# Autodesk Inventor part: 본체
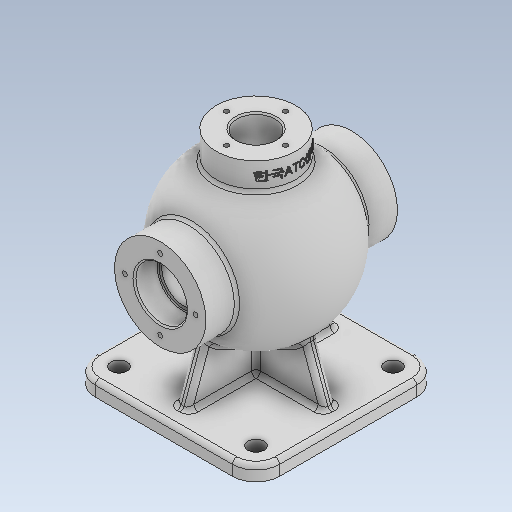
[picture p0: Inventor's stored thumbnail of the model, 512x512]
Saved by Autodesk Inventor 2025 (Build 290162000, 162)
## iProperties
Created: 2024-07
Part Number: 본체
Material: 일반
Document SubType Name: Modeling
Designer: 미서니
Density: 1 g/cm^3
Appearance: 기본값
Author: 미서니
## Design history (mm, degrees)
sketch "스케치1"
  geometry: L1 (0, -75.794)-(0, 75.794); A1 r 54 centre (0, 0) between (0, 54) and (0, -54); 4 further points
  constraints: 2 coincident, 2 end point, 2 point on circle, 2 point on line, 1 centre point, 1 midpoint, 1 vertical
  dimensions: "d3" = 54 radius of A1
revolve "회전1" sketch "스케치1" stored, may be unused: angle "d1" = 90 deg
sketch "스케치2"
  geometry: C1 r 31 at (0, 0); 1 further point
  constraints: 1 centre point, 1 coincident
  dimensions: "d2" = 62 diameter of C1
extrude "돌출1" join sketch "스케치2" stored distance "d4" = 130; taper "d5" = 0 deg
sketch "스케치3"
  geometry: C1 r 27 at (0, 0); 1 further point
  constraints: 1 centre point, 1 coincident
  dimensions: "d6" = 54 diameter of C1
extrude "돌출2" join sketch "스케치3" distance "d7" = 65; taper "d8" = 0 deg
node "작업 평면1"
sketch "스케치4"
  geometry: L1 (62.5, -62.5)-(-62.5, -62.5); L2 (-62.5, -62.5)-(-62.5, 62.5); L3 (-62.5, 62.5)-(62.5, 62.5); L4 (62.5, 62.5)-(62.5, -62.5); L5 (62.5, -62.5)-(-62.5, 62.5); L6 (-62.5, -62.5)-(62.5, 62.5); 1 further point
  constraints: 12 end point, 2 midpoint, 2 parallel, 1 horizontal, 1 perpendicular
  dimensions: "d10" = 125 distance of L2.end L3.end; "d11" = 125 distance of L1.end L2.end
extrude "돌출3" join sketch "스케치4" distance "d12" = 10; taper "d13" = 0 deg
fillet "모깎기1" dims "d14" = 16
node "작업 평면2"
sketch "스케치5"
  geometry: L1 (50.5, 4)-(-50.5, 4); L2 (-50.5, 4)-(-50.5, -4); L3 (-50.5, -4)-(50.5, -4); L4 (50.5, -4)-(50.5, 4); L5 (50.5, 4)-(-50.5, -4); L6 (-50.5, 4)-(50.5, -4); L7 (4, 50.5)-(-4, 50.5); L8 (-4, 50.5)-(-4, -50.5); L9 (-4, -50.5)-(4, -50.5); L10 (4, -50.5)-(4, 50.5); L11 (4, 50.5)-(-4, -50.5); L12 (-4, 50.5)-(4, -50.5); L13 (-62.5, 46.5)-(-62.5, -46.5) reference; L14 (-46.5, -62.5)-(46.5, -62.5) reference; 5 further points
  constraints: 24 end point, 4 midpoint, 4 parallel, 2 horizontal, 2 perpendicular
  dimensions: "d16" = 8 distance of L1.end L2.end; "d17" = 8 distance of L7.start L7.end; "d18" = 12 distance between parallel lines of L13 L2; "d19" = 12 distance between parallel lines of L14 L9
extrude "돌출4" join sketch "스케치5" stored distance "d20" = 10; taper "d21" = 0 deg
feature "면 기울기1" dims angle "d22" = 20 deg
fillet "모깎기2" dims "d23" = 3
fillet "모깎기3" dims "d24" = 3
sketch "스케치6"
  geometry: L1 (0, 159.291)-(0, -194.33); A1 r 44 centre (0, 0) between (0, 44) and (0, -44); 1 further point
  constraints: 3 point on line, 2 end point, 2 point on circle, 1 centre point, 1 coincident, 1 vertical
  dimensions: "d25" = 44 radius of A1
revolve "회전2" sketch "스케치6" stored, may be unused: angle "d26" = 90 deg
sketch "스케치7"
  geometry: C1 r 31 at (0, 0) reference; 2 further points
  constraints: 1 coincident
hole "구멍1" sketch "스케치7" at (0, 0) diameter "d27" = 30; stored, may be unused: countersink angle "d31" = 90 deg, drill point angle "d33" = 0 deg; dims "d28" = 6, "d29" = 4, "d30" = 2, "d32" = 8
sketch "스케치9"
  geometry: C1 r 31 at (0, 0) reference; 2 further points
  constraints: 1 coincident
hole "구멍3" sketch "스케치9" at (0, 0) diameter "d41" = 35; stored, may be unused: countersink angle "d45" = 90 deg, drill point angle "d47" = 0 deg; dims "d42" = 6, "d43" = 4, "d44" = 2, "d46" = 16
sketch "스케치10"
  geometry: C1 r 31 at (0, 0) reference; 2 further points
  constraints: 1 coincident
hole "구멍4" sketch "스케치10" at (0, 0) diameter "d48" = 35; stored, may be unused: countersink angle "d52" = 90 deg, drill point angle "d54" = 0 deg; dims "d49" = 6, "d50" = 4, "d51" = 2, "d53" = 16
sketch "스케치11"
  geometry: C1 r 27 at (0, 0) reference; 2 further points
  constraints: 1 coincident
hole "구멍5" sketch "스케치11" at (0, 0) diameter "d63" = 26; stored, may be unused: countersink angle "d67" = 90 deg, drill point angle "d69" = 0 deg; dims "d64" = 6, "d65" = 4, "d66" = 2, "d68" = 16
chamfer "모따기1" distance "d70" = 1; stored, may be unused: second distance "d71" = 2, angle "d72" = 45 deg
fillet "모깎기4" dims "d73" = 0.6
sketch "스케치12" dims "d74" = 48
  geometry: L1 (0, 0)-(0, 24); 1 further point
  constraints: 2 end point, 1 coincident, 1 vertical, 1 vertical alignment, 2 other
sketch "스케치13" dims "d75" = 48
  geometry: L1 (0, 0)-(0, 24); 1 further point
  constraints: 2 end point, 1 coincident, 1 vertical, 1 vertical alignment, 2 other
hole "구멍6" sketch "스케치12" diameter "d76" = 3.242; stored, may be unused: countersink angle "d80" = 90 deg, drill point angle "d82" = 120 deg; dims "d77" = 12, "d78" = 4, "d79" = 2, "d81" = 15
hole "구멍7" sketch "스케치13" diameter "d83" = 3.242; stored, may be unused: countersink angle "d87" = 90 deg, drill point angle "d89" = 120 deg; dims "d84" = 12, "d85" = 4, "d86" = 2, "d88" = 15
sketch "스케치14" dims "d93" = 40
  geometry: L1 (0, 0)-(0, -20); 1 further point
  constraints: 2 end point, 1 coincident, 1 vertical, 1 vertical alignment, 2 other
hole "구멍8" sketch "스케치14" at (0, -20) diameter "d94" = 3.242; stored, may be unused: countersink angle "d98" = 90 deg, drill point angle "d100" = 120 deg; dims "d95" = 9, "d96" = 4, "d97" = 2, "d99" = 11
sketch "스케치16"
  geometry: A1 r 13 centre (46.5, -46.5) between (46.5, -59.5) and (59.5, -46.5) reference; A2 r 13 centre (46.5, 46.5) between (59.5, 46.5) and (46.5, 59.5) reference; A3 r 13 centre (-46.5, -46.5) between (-59.5, -46.5) and (-46.5, -59.5) reference; A4 r 13 centre (-46.5, 46.5) between (-46.5, 59.5) and (-59.5, 46.5) reference; 5 further points
  constraints: 4 coincident
hole "구멍9" sketch "스케치16" at (46.5, -46.5), (46.5, 46.5), (-46.5, -46.5), (-46.5, 46.5) diameter "d104" = 11; stored, may be unused: countersink angle "d108" = 90 deg, drill point angle "d110" = 0 deg; dims "d105" = 9, "d106" = 4, "d107" = 2, "d109" = 11
node "작업 평면3"
sketch "스케치17"
  geometry: L1 (65, -27)-(65, 27) reference; 2 further points
  constraints: 1 horizontal alignment, 1 other
  dimensions: "d112" = 9 distance from line of point (56, 0) L1
feature "엠보싱1" sketch "스케치17" dims "d3" = 54, "d10" = 125, "d11" = 125, "d113" = 0.5, "d114" = 0
node "솔리드1"
pattern_circular "원형 패턴1" dims "d91" = 360 deg
pattern_circular "원형 패턴2" dims angle "d102" = 360 deg
feature "A9D066F2-1C7D-4E18-AEED-F7BC21143FA4" dims "d27" = 30, "d28" = 6, "d29" = 4, "d30" = 2, "d31" = 90 deg, "d32" = 8, "d33" = 0
other parameters: "d9" = -85, "d55" = 0.5, "d56" = 2, "d57" = 0, "d59" = 0.5, "d60" = 2, "d61" = 0
